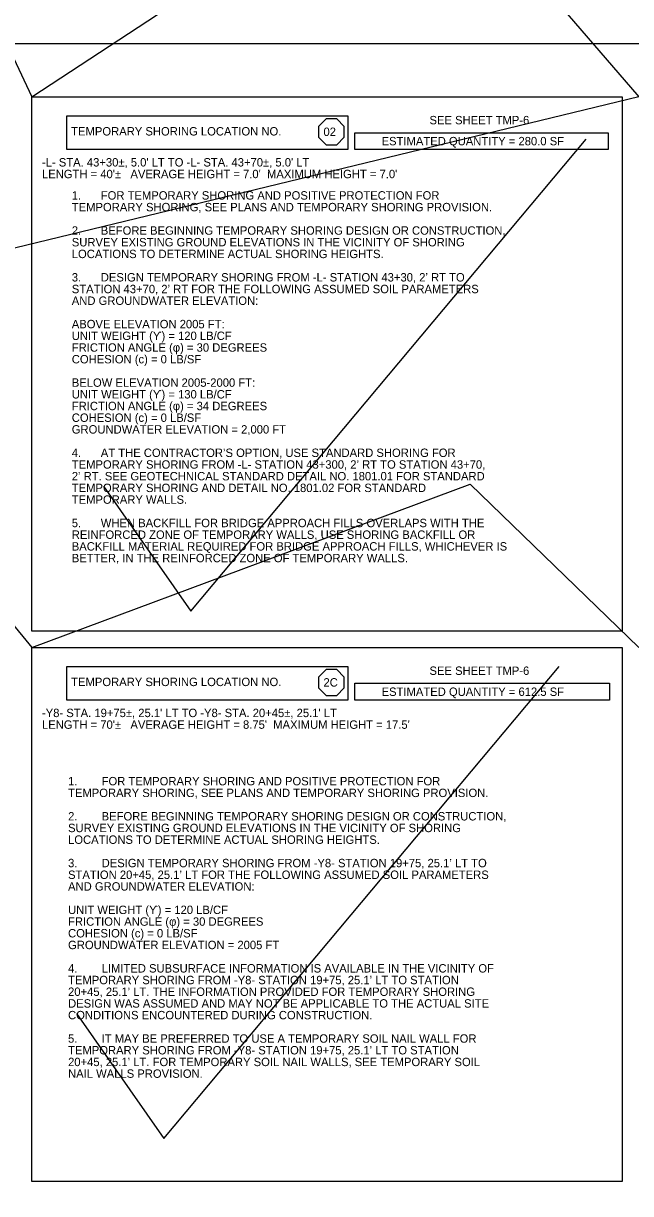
# Model space of a CAD drawing. Extents: x 2487012 to 2497594, y 369516 to 371986.
# Drawn here: x 2489515 to 2490008, y 370349 to 371299 of the extents above; entities that cross this region are included whole.
import ezdxf

# ---------------------------------------------------------------- set-up
doc = ezdxf.new("R2010")
doc.units = 0
for name, color, linetype in [('Scratch_Level_2', 7, 'Continuous'), ('Scratch_Level_6', 7, 'Continuous'), ('TC LABEL TEMP SHORING', 7, 'Continuous'), ('TC SHEET BORDER LINE THIN', 7, 'Continuous'), ('TC SHEET LAYOUT SHAPE', 7, 'Continuous'), ('TC SHEET TEXT', 7, 'Continuous')]:
    doc.layers.add(name, color=color, linetype=linetype)

msp = doc.modelspace()

# ---------------------------------------------------------------- linework, layer by layer
at = {"layer": 'Scratch_Level_2'}
for points in [[(2489580.09, 370922.97), (2489650.88, 370821.56), (2489971.89, 371204.68)], [(2489558.28, 370495.03), (2489629.08, 370393.62), (2489950.08, 370776.74)]]:
    msp.add_lwpolyline(points, dxfattribs=at)
at = {"layer": 'Scratch_Level_6'}
msp.add_lwpolyline([(2489016.56, 371282.27), (2489028.88, 371239.13), (2489430.44, 371433.43), (2489521.78, 371239.13), (2489836.55, 371445.42), (2490014.68, 371239.13), (2488843.26, 370955.22), (2489028.88, 370792.26), (2489389.17, 370953.89), (2489521.78, 370792.26), (2489877.82, 370924.58), (2490014.68, 370792.26)], dxfattribs=at)
at = {"layer": 'TC LABEL TEMP SHORING'}
for p, q in [((2489760.74, 371221.17), (2489754.65, 371215.01)), ((2489754.65, 371215.01), (2489754.65, 371206.28)), ((2489769.35, 371221.17), (2489760.74, 371221.17)), ((2489775.43, 371215.01), (2489769.35, 371221.17)), ((2489775.43, 371206.28), (2489775.43, 371215.01)), ((2489754.65, 371206.28), (2489760.74, 371200.12)), ((2489769.35, 371200.12), (2489775.43, 371206.28)), ((2489760.74, 371200.12), (2489769.35, 371200.12)), ((2489760.74, 370774.3), (2489754.65, 370768.13)), ((2489754.65, 370768.13), (2489754.65, 370759.41)), ((2489769.35, 370774.3), (2489760.74, 370774.3)), ((2489775.43, 370768.13), (2489769.35, 370774.3)), ((2489775.43, 370759.41), (2489775.43, 370768.13)), ((2489754.65, 370759.41), (2489760.74, 370753.24)), ((2489769.35, 370753.24), (2489775.43, 370759.41)), ((2489760.74, 370753.24), (2489769.35, 370753.24))]:
    msp.add_line(p, q, dxfattribs=at)
at = {"layer": 'TC SHEET BORDER LINE THIN'}
for points in [[(2489521.78, 371239.13), (2490001.22, 371239.13), (2490001.22, 370805.5), (2489521.78, 370805.5)], [(2489550.27, 371223.55), (2489778.32, 371223.55), (2489778.32, 371196.29), (2489550.27, 371196.29)], [(2489784.09, 371209.92), (2489989.87, 371209.92), (2489989.87, 371196.29), (2489784.09, 371196.29)], [(2489521.78, 370792.26), (2490001.22, 370792.26), (2490001.22, 370358.63), (2489521.78, 370358.63)], [(2489550.27, 370776.68), (2489778.32, 370776.68), (2489778.32, 370749.42), (2489550.27, 370749.42)], [(2489784.09, 370763.05), (2489990.88, 370763.05), (2489990.88, 370749.42), (2489784.09, 370749.42)]]:
    msp.add_lwpolyline(points, close=True, dxfattribs=at)
at = {"layer": 'TC SHEET LAYOUT SHAPE'}
msp.add_lwpolyline([(2489016.56, 370690.84), (2489016.56, 371000.16), (2489016.56, 371272.27), (2489026.56, 371282.27), (2489469.58, 371282.27), (2489940.56, 371282.27), (2490261.56, 371282.27), (2490261.56, 371202.27), (2490346.56, 371202.27), (2490346.56, 371250.27), (2490506.56, 371250.27), (2490506.56, 370915.3), (2490506.56, 370636.1), (2490506.56, 370384.77), (2490151.56, 370384.77), (2490151.56, 370242.27), (2489778.38, 370242.27), (2489608.92, 370242.27), (2489256.14, 370242.27), (2489016.56, 370242.27)], close=True, dxfattribs=at)

# ---------------------------------------------------------------- texts
at = {"layer": 'TC LABEL TEMP SHORING'}
for s, p in [('02', (2489758.63, 371207.28)), ('2C', (2489758.63, 370760.41))]:
    msp.add_text(s, height=6.814, dxfattribs=at).set_placement(p)
at = {"layer": 'TC SHEET BORDER LINE THIN'}
for s, height, p in [('1.', 6.814, (2489554.33, 371155.64)), ('FOR TEMPORARY SHORING AND POSITIVE PROTECTION FOR ', 6.8137, (2489577.87, 371155.64)), ('TEMPORARY SHORING, SEE PLANS AND TEMPORARY SHORING PROVISION.', 6.8137, (2489554.33, 371146.14)), ('2.', 6.814, (2489554.33, 371127.15)), ('BEFORE BEGINNING TEMPORARY SHORING DESIGN OR CONSTRUCTION, ', 6.8137, (2489577.87, 371127.15)), ('SURVEY EXISTING GROUND ELEVATIONS IN THE VICINITY OF SHORING ', 6.8137, (2489554.33, 371117.66)), ('LOCATIONS TO DETERMINE ACTUAL SHORING HEIGHTS.', 6.8137, (2489554.33, 371108.16)), ('3.', 6.814, (2489554.33, 371089.18)), ('DESIGN TEMPORARY SHORING FROM -L- STATION 43+30, 2’ RT TO ', 6.8137, (2489577.87, 371089.18)), ('STATION 43+70, 2’ RT FOR THE FOLLOWING ASSUMED SOIL PARAMETERS ', 6.8137, (2489554.33, 371079.68)), ('AND GROUNDWATER ELEVATION:', 6.8137, (2489554.33, 371070.19)), ('ABOVE ELEVATION 2005 FT:', 6.8137, (2489554.33, 371051.2)), ('UNIT WEIGHT (ϒ) = 120 LB/CF', 6.8137, (2489554.33, 371041.7)), ('FRICTION ANGLE (φ) = 30 DEGREES', 6.8137, (2489554.33, 371032.21)), ('COHESION (c) = 0 LB/SF', 6.8137, (2489554.33, 371022.71)), ('BELOW ELEVATION 2005-2000 FT:', 6.8137, (2489554.33, 371003.73)), ('UNIT WEIGHT (ϒ) = 130 LB/CF', 6.8137, (2489554.33, 370994.23)), ('FRICTION ANGLE (φ) = 34 DEGREES', 6.8137, (2489554.33, 370984.74)), ('COHESION (c) = 0 LB/SF', 6.8137, (2489554.33, 370975.24)), ('GROUNDWATER ELEVATION = 2,000 FT', 6.8137, (2489554.33, 370965.75)), ('4.', 6.814, (2489554.33, 370946.76)), ('AT THE CONTRACTOR’S OPTION, USE STANDARD SHORING FOR ', 6.8137, (2489577.87, 370946.76)), ('TEMPORARY SHORING FROM -L- STATION 43+300, 2’ RT TO STATION 43+70, ', 6.8137, (2489554.33, 370937.27)), ('2’ RT. SEE GEOTECHNICAL STANDARD DETAIL NO. 1801.01 FOR STANDARD ', 6.8137, (2489554.33, 370927.77)), ('TEMPORARY SHORING AND DETAIL NO. 1801.02 FOR STANDARD ', 6.8137, (2489554.33, 370918.28)), ('TEMPORARY WALLS.', 6.8137, (2489554.33, 370908.78)), ('5.', 6.814, (2489554.33, 370889.79)), ('WHEN BACKFILL FOR BRIDGE APPROACH FILLS OVERLAPS WITH THE ', 6.8137, (2489577.87, 370889.79)), ('REINFORCED ZONE OF TEMPORARY WALLS, USE SHORING BACKFILL OR ', 6.8137, (2489554.33, 370880.3)), ('BACKFILL MATERIAL REQUIRED FOR BRIDGE APPROACH FILLS, WHICHEVER IS ', 6.8137, (2489554.33, 370870.8)), ('BETTER, IN THE REINFORCED ZONE OF TEMPORARY WALLS.', 6.8137, (2489554.33, 370861.31)), ('1.', 6.814, (2489551.31, 370680.25)), ('FOR TEMPORARY SHORING AND POSITIVE PROTECTION FOR ', 6.8137, (2489578.57, 370680.25)), ('TEMPORARY SHORING, SEE PLANS AND TEMPORARY SHORING PROVISION.', 6.8137, (2489551.31, 370670.75)), ('2.', 6.814, (2489551.31, 370651.76)), ('BEFORE BEGINNING TEMPORARY SHORING DESIGN OR CONSTRUCTION, ', 6.8137, (2489578.57, 370651.76)), ('SURVEY EXISTING GROUND ELEVATIONS IN THE VICINITY OF SHORING ', 6.8137, (2489551.31, 370642.27)), ('LOCATIONS TO DETERMINE ACTUAL SHORING HEIGHTS.', 6.8137, (2489551.31, 370632.77)), ('3.', 6.814, (2489551.31, 370613.78)), ('DESIGN TEMPORARY SHORING FROM -Y8- STATION 19+75, 25.1’ LT TO ', 6.8137, (2489578.57, 370613.78)), ('STATION 20+45, 25.1’ LT FOR THE FOLLOWING ASSUMED SOIL PARAMETERS ', 6.8137, (2489551.31, 370604.29)), ('AND GROUNDWATER ELEVATION:', 6.8137, (2489551.31, 370594.8)), ('UNIT WEIGHT (ϒ) = 120 LB/CF', 6.8137, (2489551.31, 370575.81)), ('FRICTION ANGLE (φ) = 30 DEGREES', 6.8137, (2489551.31, 370566.31)), ('COHESION (c) = 0 LB/SF', 6.8137, (2489551.31, 370556.82)), ('GROUNDWATER ELEVATION = 2005 FT', 6.8137, (2489551.31, 370547.32)), ('4.', 6.814, (2489551.31, 370528.34)), ('LIMITED SUBSURFACE INFORMATION IS AVAILABLE IN THE VICINITY OF ', 6.8137, (2489578.57, 370528.34)), ('TEMPORARY SHORING FROM -Y8- STATION 19+75, 25.1’ LT TO STATION ', 6.8137, (2489551.31, 370518.84)), ('20+45, 25.1’ LT. THE INFORMATION PROVIDED FOR TEMPORARY SHORING ', 6.8137, (2489551.31, 370509.35)), ('DESIGN WAS ASSUMED AND MAY NOT BE APPLICABLE TO THE ACTUAL SITE ', 6.8137, (2489551.31, 370499.85)), ('CONDITIONS ENCOUNTERED DURING CONSTRUCTION.', 6.8137, (2489551.31, 370490.36)), ('5.', 6.814, (2489551.31, 370471.37)), ('IT MAY BE PREFERRED TO USE A TEMPORARY SOIL NAIL WALL FOR ', 6.8137, (2489578.57, 370471.37)), ('TEMPORARY SHORING FROM -Y8- STATION 19+75, 25.1’ LT TO STATION ', 6.8137, (2489551.31, 370461.87)), ('20+45, 25.1’ LT. FOR TEMPORARY SOIL NAIL WALLS, SEE TEMPORARY SOIL ', 6.8137, (2489551.31, 370452.38)), ('NAIL WALLS PROVISION.', 6.8137, (2489551.31, 370442.89))]:
    msp.add_text(s, height=height, dxfattribs=at).set_placement(p)
at = {"layer": 'TC SHEET TEXT'}
for s, p in [('SEE SHEET TMP-6', (2489844.71, 371216.75)), ('TEMPORARY SHORING LOCATION NO.', (2489553.84, 371207.68)), ('ESTIMATED QUANTITY = 280.0 SF', (2489805.81, 371199.7)), ("-L- STA. 43+30±, 5.0' LT TO -L- STA. 43+70±, 5.0' LT", (2489530.12, 371182.51)), ("LENGTH = 40'±   AVERAGE HEIGHT = 7.0'  MAXIMUM HEIGHT = 7.0'", (2489530.12, 371173.02)), ('SEE SHEET TMP-6', (2489844.71, 370769.88)), ('TEMPORARY SHORING LOCATION NO.', (2489553.84, 370760.81)), ('ESTIMATED QUANTITY = 612.5 SF', (2489805.81, 370752.83)), ("-Y8- STA. 19+75±, 25.1' LT TO -Y8- STA. 20+45±, 25.1' LT", (2489530.12, 370735.64)), ("LENGTH = 70'±   AVERAGE HEIGHT = 8.75'  MAXIMUM HEIGHT = 17.5'", (2489530.12, 370726.15))]:
    msp.add_text(s, height=6.8137, dxfattribs=at).set_placement(p)

doc.saveas('drawing.dxf')
